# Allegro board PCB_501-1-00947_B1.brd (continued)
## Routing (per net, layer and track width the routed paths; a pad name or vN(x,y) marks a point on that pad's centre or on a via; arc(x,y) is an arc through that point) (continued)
MIPI_VREG_0P4V: length 1.2
  TOP w0.254: v2(55.77,85.77) 55.69,85.85 U7.H18
  BOTTOM w0.254: 55.37,86.26 55.77,85.86 v2(55.77,85.77)
MX7_ONOFF: length 75.1
  TOP w0.102: 69.48,88.95 v2(69.48,88.95) ; 69.48,88.95 U7.AC8 69.48,88.95
  TOP w0.127: C367.1 R249.1 ; R249.1 97.9,67.84 SW6.3 SW6.4 ; R249.1 92.74,67.84 92.3,68.28 92.3,70.08 89.43,72.95 89.43,81.59 91.94,84.09 96.01,84.09 98.39,86.47 v1(98.39,86.99)
  L6_INT_2 w0.102: 71.74,89.17 71.51,88.95 v2(69.48,88.95)
  L6_INT_2 w0.127: 71.74,89.17 75.13,89.17 77.66,86.65 78.01,86.65 78.86,85.8 81.77,85.8 82.62,86.65 87.33,86.65 88.18,87.51 97.88,87.51 v1(98.39,86.99)
MX7_RST_B: length 17.1
  TOP w0.254: v1(87.58,86.06) 84.66,88.97 84.66,92.44 86.33,94.11 D21.1 ; R347.1 C368.1 88.61,81.68 v1(87.9,82.39)
  L6_INT_2 w0.254: v1(87.9,82.39) 87.58,82.71 v1(87.58,86.06)
NVCC_DRAM_CKE: length 8.9
  TOP w0.137: v2(61,94.24) 60.99,94.24 60.99,93.72
  L6_INT_2 w0.127: v2(61,94.24) 60.46,94.24 59.77,94.93 59.77,94.93 59.56,95.15 59.55,95.15 59.24,95.46 59.24,95.46 59.03,95.68 58.31,95.68
  L6_INT_2 w0.305: v2(55.59,95.37) 55.9,95.68 58.31,95.68
  BOTTOM w0.254: R85.1 54.46,95.57 54.62,95.73 55.23,95.73 v2(55.59,95.37) 55.59,94.94 C140.1
OTG1_CHD_B: length 6.8
  TOP w0.102: U7.C7 58.35,77.81 v2(58.35,77.81)
  BOTTOM w0.102: 56.6,77.29 57.33,78.02 57.33,78.38 57.73,78.77 57.89,78.77 58.34,78.32 58.34,77.82 v2(58.35,77.81)
  BOTTOM w0.127: TP48.1 55.21,75.54 56.6,76.92 56.6,77.29
OTG1_REXT: length 5.8
  TOP w0.127: v1(55.77,73.18) 56.46,73.18 57.04,73.76 57.04,75.98 U7.A7
  BOTTOM w0.127: v1(55.77,73.18) 55.74,73.18 R66.2
OTG2_REXT: length 5.6
  TOP w0.127: R70.2 52.87,74.78 52.83,74.82 52.83,75.49 53.48,76.15 53.65,76.15 54.68,77.18 54.68,77.86 U7.A11
OTG_VBUS: length 1.5
  TOP w0.508: FB18.2 49.91,7.57 C298.1
  vias: v1(47.72,10.16) v1(47.72,9.02)
OTG_VBUS_CTRL: length 2.5
  BOTTOM w0.508: Q25.3 51,16.13 R570.1 50.88,15.99 Q24.1
OUT3: length 2.5
  TOP w0.254: v1(99.86,39.86) 99.79,39.79 U24.30
  BOTTOM w0.127: C276.1 100.34,39.86 v1(99.86,39.86)
OVRPRTC: length 2.4
  TOP w0.254: Q5.1 41.42,99.11 R8.2 40.99,99.59 R6.1
OVRPRTC_LED: length 2.9
  TOP w0.254: Q5.3 40.04,96.65 D2.1
OVRPRTC_LED_PWR: length 1.3
  TOP w0.254: R4.2 36.07,97.9 D2.2
PCIE_CLK_GEN_SCL: length 6.1
  TOP w0.137: v1(76.34,101.75) 76.34,101.67 U42.8
  BOTTOM w0.137: v1(76.34,101.75) 76.34,102.99 R595.1
PCIE_CLK_GEN_SDA: length 6.4
  TOP w0.137: U42.9 78.29,99.09 76.06,101.32 v1(75.81,101.32)
  BOTTOM w0.137: R596.1 75.81,103.6 v1(75.81,101.32)
PCIE_CLKGEN_SS_SEL: length 2
  TOP w0.127: R604.1 82.48,95.53 U42.23
PCIE_CTXM: length 2.7
  BOTTOM w0.137: C207.2 101.98,72.77 arc(101.9,72.89) 101.87,73.03 101.87,74.34 arc(101.93,74.67) J8.31
PCIE_CTXP: length 2.7
  BOTTOM w0.137: C208.2 101.47,72.77 arc(101.55,72.89) 101.58,73.03 101.58,74.34 arc(101.51,74.67) J8.33
PCIE_DIS_B: length 47.3
  TOP w0.102: U7.T2 68.42,81.55 68.98,80.99 68.98,80.45 69.32,80.11 69.89,80.11 v1(70.25,79.76)
  L6_INT_2 w0.102: v1(70.25,79.76) 70.86,79.76
  L6_INT_2 w0.127: v1(104.68,86.15) 92.56,86.15 85.72,79.31 82.43,79.31 81.48,78.36 72.99,78.36 71.59,79.76 70.86,79.76
  BOTTOM w0.127: J8.20 106.52,84.47 106.9,84.85 106.9,86.02 106.31,86.61 105.14,86.61 v1(104.68,86.15)
PCIE_REFCLK_N: length 10.6
  TOP w0.104: U7.AE10 68.95,91.19 69.42,91.67 arc(69.48,91.71) 69.55,91.72 70.05,91.72 70.16,91.6 70.46,91.6 70.58,91.72 70.88,91.72 71,91.6 71.3,91.6 71.41,91.72 71.42,91.72 arc(71.68,91.77) 71.91,91.92 71.91,91.93 arc(71.94,91.95) 71.96,91.97 arc(72.02,92.03) 72.07,92.08 72.07,92.08 arc(72.21,92.18) 72.38,92.21 R608.1 72.77,92.55 72.71,92.62 arc(72.68,92.65) 72.68,92.69 72.68,92.76 arc(72.69,92.82) 72.72,92.88 72.91,93.06 arc(72.94,93.08) 72.98,93.09 73.1,93.09 arc(73.14,93.08) 73.17,93.06 73.24,93 R607.2 73.56,93.32 arc(73.59,93.47) 73.68,93.6 arc(73.78,93.67) 73.91,93.69 74.38,93.69 arc(74.59,93.65) 74.77,93.53 74.98,93.32 arc(75.23,93.15) 75.53,93.1 77.22,93.1 R633.2
PCIE_REFCLK_P: length 10.5
  TOP w0.104: U7.AD10 68.61,90.73 68.61,91.21 68.61,91.25 69.23,91.87 arc(69.37,91.96) 69.55,92 71.29,92 arc(71.81,92.21) 72.03,92.73 72.03,92.92 72.22,92.92 arc(72.26,92.93) 72.29,92.95 72.8,93.46 arc(72.83,93.51) 72.84,93.58 R605.2 73.32,93.73 arc(73.41,93.75) 73.48,93.79 arc(73.68,93.93) 73.91,93.97 74.38,93.97 arc(74.7,93.91) 74.96,93.73 75.17,93.52 arc(75.34,93.41) 75.53,93.37 76.22,93.37 arc(76.28,93.39) 76.33,93.42 76.36,93.46 arc(76.39,93.49) 76.39,93.53 R632.2
PCIE_REFCLKOUT_N: length 71.8
  TOP w0.104: R598.2 75.12,94.96 arc(75.02,94.94) 74.93,94.9 74.93,94.91 arc(74.76,94.82) 74.58,94.79 74.44,94.79 arc(74.07,94.87) 73.77,95.07 73.7,95.14 arc(73.6,95.2) 73.5,95.22 v1(73.3,95.22) ; 67.89,90.01 68.42,90.01 v2(68.42,90.01)
  L3_INT_1 w0.117: v1(73.3,95.22) 73.3,95.39 arc(73.27,95.52) 73.19,95.64 arc(73.04,95.74) 72.85,95.78 72.68,95.78 arc(72.51,95.75) 72.38,95.66 72.05,95.32 arc(71.95,95.19) 71.88,95.04 arc(71.87,94.96) 71.87,94.89 71.87,93.29 arc(71.77,92.83) 71.51,92.44 arc(71.15,92.2) 70.73,92.11 arc(70.43,92.05) 70.18,91.88 68.42,90.13 v2(68.42,90.01)
  BOTTOM w0.104: R645.1 113.21,70.3 arc(113.12,70.18) 113.09,70.03 113.09,69.9 arc(113,69.46) 112.76,69.09 112.14,68.47 arc(110.69,67.51) 108.99,67.17 93.13,67.17 93.05,67.09 92.67,67.09 92.6,67.17 92.29,67.17 92.2,67.07 91.86,67.07 91.76,67.17 91.76,67.17 arc(89.96,67.52) 88.44,68.54 86.94,70.04 arc(85.43,72.3) 84.9,74.96 84.9,82.97 arc(84.73,83.83) 84.25,84.56 73.78,95.02 arc(73.56,95.17) v1(73.3,95.22)
PCIE_REFCLKOUT_N0: length 3.9
  BOTTOM w0.104: R645.2 113.13,71.89 arc(113.09,71.95) 113.07,72.02 arc(113.06,72.06) 113.06,72.09 arc(113.08,72.21) 113.15,72.32 R634.2 113.33,72.75 arc(113.13,73.05) 113.06,73.4 113.06,74.32 arc(113.13,74.66) J8.11
PCIE_REFCLKOUT_P: length 71.8
  TOP w0.104: U7.AB10 67.89,89.48 v2(67.89,89.48) ; R597.2 74.83,95.26 arc(74.82,95.21) 74.79,95.16 arc(74.7,95.09) 74.58,95.07 74.44,95.07 arc(74.18,95.12) 73.96,95.27 73.96,95.27 arc(73.83,95.47) v1(73.78,95.71)
  L3_INT_1 w0.117: v1(73.78,95.71) 73.7,95.71 arc(73.53,95.74) 73.39,95.83 arc(73.14,96) 72.85,96.06 72.68,96.06 arc(72.41,96) 72.18,95.85 71.85,95.52 arc(71.7,95.33) 71.61,95.1 71.59,95.08 71.59,93.29 arc(71.52,92.94) 71.31,92.63 arc(71.05,92.45) 70.73,92.39 arc(70.33,92.31) 69.98,92.08 68.08,90.18 arc(68.06,90.14) 68.05,90.1 68.05,89.68 arc(68.04,89.64) 68.01,89.6 v2(67.89,89.48)
  BOTTOM w0.104: R644.1 112.72,70.22 arc(112.79,70.12) 112.81,70.01 112.81,69.9 arc(112.75,69.57) 112.56,69.29 111.94,68.67 arc(110.59,67.76) 108.99,67.45 91.76,67.45 arc(90.07,67.78) 88.64,68.74 87.14,70.24 arc(85.69,72.41) 85.18,74.96 85.18,82.97 arc(84.99,83.94) 84.45,84.76 73.98,95.22 arc(73.98,95.22) 73.98,95.22 arc(73.83,95.45) v1(73.78,95.71)
PCIE_REFCLKOUT_P0: length 3.9
  BOTTOM w0.104: R644.2 112.69,71.85 arc(112.76,71.95) 112.78,72.06 112.78,72.17 arc(112.77,72.23) 112.74,72.28 R635.2 112.46,72.69 arc(112.7,73.05) 112.78,73.46 112.78,74.32 arc(112.71,74.66) J8.13
PCIE_REXT: length 3.3
  TOP w0.102: v2(65.22,91.07) 65.24,91.06 U7.AA13
  BOTTOM w0.102: v2(65.22,91.07) 65.79,91.07 66.77,92.05 67.59,92.05 R80.2
PCIE_RST_B: length 45.8
  TOP w0.102: 70.9,80.09 68.4,82.58 U7.T3
  TOP w0.127: v1(73.35,77.14) 73.17,77.14 71.85,78.46 71.85,78.82 71.09,79.59 71.09,79.9 70.9,80.09
  L6_INT_2 w0.127: v1(103.73,85.47) 103.52,85.68 92.67,85.68 86.02,79.03 82.54,79.03 81.59,78.08 73.86,78.08 73.35,77.57 v1(73.35,77.14)
  BOTTOM w0.127: J8.22 105.72,83.96 104.21,85.47 v1(103.73,85.47)
PCIE_RX_N: length 71.2
  TOP w0.102: U7.AE11 68.42,91.74 68.86,92.19 69.02,92.19 69.23,92.4 69.23,92.55 69.55,92.88
  TOP w0.137: 69.55,92.88 69.88,93.2 v1(70.46,93.2)
  BOTTOM w0.137: R96.1 arc(105.47,71.52) 105.43,71.5 105.14,71.2 arc(105.09,71.14) 105.08,71.06 105.08,70.85 arc(105.11,70.7) 105.19,70.58 105.24,70.53 arc(105.52,70.34) 105.86,70.27 106.47,70.27 arc(107.34,70.45) 108.07,70.94 108.08,70.95 arc(108.78,71.99) 109.02,73.23 109.02,73.51 108.87,73.65 108.87,74.05 109.02,74.2 109.02,74.67 108.82,74.87 108.82,75.22 109.02,75.42 109.02,75.69 arc(108.93,76.17) 108.65,76.57 arc(107.56,77.3) 106.28,77.56 106.01,77.56 105.85,77.39 105.46,77.39 105.3,77.56 104.91,77.56 104.75,77.39 104.37,77.39 104.2,77.56 103.82,77.56 103.65,77.39 103.27,77.39 103.1,77.56 102.72,77.56 102.55,77.39 102.17,77.39 102,77.56 97.41,77.56 97.25,77.4 96.89,77.4 96.73,77.56 96.37,77.56 96.21,77.4 95.85,77.4 95.69,77.56 95.34,77.56 95.17,77.4 94.82,77.4 94.65,77.56 94.3,77.56 94.14,77.4 93.78,77.4 93.62,77.56 93.35,77.56 arc(92.35,77.76) 91.49,78.33 91.11,78.71 arc(90.43,79.73) 90.19,80.93 90.19,81.6 arc(88.91,88.03) 85.27,93.49 83.04,95.71 82.81,95.71 82.54,95.99 82.54,96.22 82.27,96.49 82.04,96.49 81.76,96.76 81.76,96.99 81.49,97.27 81.26,97.27 80.99,97.54 80.99,97.77 79.55,99.21 arc(78.73,99.76) 77.76,99.95 76.68,99.95 76.52,99.79 76.16,99.79 76,99.95 75.74,99.95 arc(74.78,99.76) 73.96,99.21 73.78,99.03 73.78,98.8 73.52,98.55 73.3,98.55 73.04,98.29 73.04,98.07 72.79,97.81 72.56,97.81 71.54,96.79 arc(71.22,96.32) 71.11,95.76 71.11,94.78 arc(71,94.2) 70.67,93.71 arc(70.51,93.48) v1(70.46,93.2)
PCIE_RX_P: length 71.4
  TOP w0.102: 69.26,92.99 69.17,92.91 69.17,92.86 68.16,91.85 68.16,91.83 68.08,91.74 68.08,91.33 67.89,91.14 U7.AD11
  TOP w0.137: 69.26,92.99 69.98,93.72 v1(69.98,93.88)
  BOTTOM w0.137: v1(69.98,93.88) 70.17,93.88 arc(70.36,93.91) 70.54,94 arc(70.75,94.37) 70.82,94.78 70.82,95.76 arc(70.95,96.43) 71.33,96.99 73.76,99.42 arc(74.67,100.03) 75.74,100.24 77.76,100.24 arc(78.84,100.03) 79.75,99.41 85.48,93.69 arc(89.18,88.15) 90.48,81.6 90.48,80.93 arc(90.7,79.84) 91.32,78.92 91.7,78.54 arc(92.46,78.03) 93.35,77.85 106.28,77.85 arc(107.67,77.57) 108.86,76.78 arc(109.2,76.28) 109.31,75.69 109.31,73.23 arc(109.05,71.88) 108.29,70.74 arc(108.28,70.74) 108.28,70.73 arc(107.45,70.18) 106.47,69.98 105.86,69.98 arc(105.41,70.07) 105.04,70.32 104.98,70.38 arc(104.84,70.59) 104.79,70.85 104.79,71.06 arc(104.77,71.14) 104.73,71.2 104.43,71.5 arc(104.4,71.52) R97.1
PCIE_RXN_R: length 2.7
  BOTTOM w0.137: R96.2 105.23,72.77 arc(105.11,72.95) 105.07,73.15 105.07,74.34 arc(105.13,74.67) J8.23
PCIE_RXP_R: length 2.7
  BOTTOM w0.137: R97.2 104.71,72.84 arc(104.76,72.91) 104.78,73 104.78,74.34 arc(104.71,74.67) J8.25
PCIE_SMB_CLK: length 3.2
  BOTTOM w0.127: R506.1 102.65,86.24 102.65,85.29 102.58,85.22 102.58,83.21 J8.30
PCIE_SMB_DATA: length 3.3
  BOTTOM w0.127: R504.1 101.48,86.26 101.48,84.92 101.72,84.68 J8.32
PCIE_TX_N: length 56.4
  TOP w0.137: v2(67.89,90.54) 67.89,90.54 67.36,90.54
  BOTTOM w0.137: v2(67.89,90.54) arc(67.93,90.72) 68.03,90.88 69.24,92.09 arc(69.45,92.24) 69.69,92.33 arc(69.79,92.34) 69.89,92.36 arc(69.96,92.36) 70.02,92.36 70.97,92.36 arc(71.43,92.45) 71.82,92.71 72.01,92.9 arc(72.25,93.26) 72.34,93.7 72.34,94.85 arc(72.48,95.55) 72.88,96.15 73.17,96.45 arc(73.5,96.67) 73.9,96.75 73.92,96.75 arc(74.31,96.67) 74.64,96.45 74.83,96.26 74.83,96.05 75.11,95.76 75.32,95.76 75.61,95.48 75.61,95.27 75.89,94.99 76.1,94.99 76.38,94.7 76.38,94.49 76.67,94.21 76.88,94.21 84.46,86.63 arc(86.19,84.04) 86.8,80.98 86.8,77.59 arc(87.38,74.67) 89.03,72.2 89.12,72.11 arc(92.33,69.96) 96.12,69.21 96.4,69.21 96.55,69.06 96.95,69.06 97.1,69.21 97.5,69.21 97.65,69.06 98.05,69.06 98.19,69.21 99.21,69.21 arc(100.35,69.43) 101.31,70.07 101.58,70.35 arc(101.79,70.66) 101.87,71.03 arc(101.89,71.13) 101.94,71.22 102.2,71.48 arc(102.23,71.5) C207.1
PCIE_TX_P: length 56.4
  TOP w0.137: v2(67.36,90.01) 67.36,90.01 66.83,90.01 U7.AB11
  BOTTOM w0.137: C208.1 arc(101.21,71.5) 101.24,71.48 101.49,71.22 arc(101.55,71.13) 101.57,71.03 arc(101.52,70.77) 101.38,70.56 101.1,70.28 arc(100.23,69.7) 99.21,69.5 96.12,69.5 arc(92.44,70.23) 89.32,72.32 89.24,72.4 arc(87.65,74.78) 87.09,77.59 87.09,80.98 arc(86.46,84.15) 84.66,86.84 74.84,96.66 arc(74.42,96.94) 73.92,97.04 73.9,97.04 arc(73.39,96.94) 72.97,96.65 72.67,96.36 arc(72.21,95.67) 72.05,94.85 72.05,93.7 arc(71.98,93.38) 71.8,93.11 71.62,92.92 arc(71.32,92.72) 70.97,92.65 70.02,92.65 arc(69.88,92.65) 69.73,92.63 arc(69.68,92.62) 69.64,92.61 arc(69.31,92.5) 69.03,92.29 67.6,90.86 arc(67.54,90.76) 67.51,90.65 67.51,90.38 arc(67.47,90.18) v2(67.36,90.01)
PCIE_UIM_CLK: length 15.9
  TOP w0.127: J7.C3 104.87,91.86 104.87,91.19 109.52,86.54 v1(112.92,86.54)
  BOTTOM w0.127: J8.12 v1(112.92,86.54)
PCIE_UIM_DATA: length 19.8
  TOP w0.137: J7.C7 127.6,92.46 127.6,92.09 120.67,85.16 114.75,85.16 114.31,84.72 v1(113.79,84.72)
  BOTTOM w0.137: v1(113.79,84.72) 113.72,84.65 J8.10
PCIE_UIM_PWR: length 16.5
  TOP w0.508: C571.1 103.26,88.39 J7.C1 106.34,88.07 108.98,85.43 114.35,85.43 v1(114.52,85.6)
  BOTTOM w0.508: J8.8 v1(114.52,85.6)
PCIE_UIM_RST: length 12.4
  TOP w0.127: v1(105.08,89.71) 104.56,89.71 103.66,90.61 J7.C2
  BOTTOM w0.127: J8.14 112.12,84.43 110.83,85.72 109.07,85.72 v1(105.08,89.71)
PCIE_UIM_VPP: length 21.3
  TOP w0.137: J7.C6 121.81,84.13 111.77,84.13 111.32,84.58 v1(111.32,84.6)
  BOTTOM w0.137: J8.16 v1(111.32,84.6)
PCIE_USB_DM: length 3.3
  BOTTOM w0.127: FL3.4 100.06,86.05 99.8,85.79 99.8,84.6 100.12,84.28 J8.36
PCIE_USB_DP: length 3.3
  BOTTOM w0.127: FL3.1 99.26,86.02 99.53,85.75 99.53,84.49 99.32,84.29 J8.38
PHY_CLKOUT: length 10.9
  TOP w0.127: TP62.1 v1(47.72,34.29) ; v1(41.11,33.4) 40.22,34.29 U13.18
  BOTTOM w0.127: v1(47.72,34.29) 46.67,34.29 45.78,33.4 v1(41.11,33.4)
PHY_CT: length 3.1
  TOP w0.508: J27.1 22.55,19.86 C576.1
PHY_GPIO0: length 7.4
  TOP w0.127: R664.1 R666.2 26.61,37.21 30.9,37.21 31.82,36.29 U13.39
PHY_GPIO1: length 7.4
  TOP w0.127: U13.40 31.85,35.79 31.8,35.84 31.77,35.84 30.81,36.8 27.02,36.8 R667.2 R665.1
PHY_INT_B: length 2.2
  TOP w0.127: R680.1 30.83,33.53 31.1,33.79 U13.44
PHY_JTAG: length 4.8
  TOP w0.127: 39.17,36.29 39.2,36.29 39.49,36.01 39.49,35.58 39.2,35.29 U13.20 ; 39.17,36.29 U13.22 ; 39.17,36.29 39.28,36.41 39.28,36.59 39.08,36.79 38.95,36.79 ; v1(39.81,36.91) 39.77,36.86 39.02,36.86 38.95,36.79 ; 38.95,36.79 U13.23
  BOTTOM w0.127: R741.1 40.07,37.16 v1(39.81,36.91)
PHY_LED0: length 12.6
  TOP w0.127: v1(24.6,33.78) 23.73,34.66 D14.2 ; U13.47 32.07,32.26 31.38,32.26 31.06,31.95 28.74,31.95 28.03,31.24 R668.2 R663.1 26.89,31.62 27.3,32.03 v1(27.32,32.03)
  BOTTOM w0.127: v1(24.6,33.78) 26.35,32.03 v1(27.32,32.03)
PHY_LED1: length 46.7
  TOP w0.127: J27.13 30.6,8.64 20.03,8.64 19.02,9.65 19.02,23.24 24.1,28.32 24.1,30.73 24.58,31.22 R301.1 R307.2 25.75,31.24 27.03,32.53 27.63,32.53 27.72,32.44 30.88,32.44 31.24,32.79 U13.46
PHY_LED2: length 40.6
  TOP w0.127: J27.12 24.25,6.83 22.95,8.13 20.03,8.13 18.7,9.46 18.7,27.6 R302.1 R308.2 25.14,32.89 30.7,32.89 31.1,33.29 U13.45
PHY_MDI_A_M: length 19.7
  TOP w0.104: J27.3 25.27,19.46 24.92,18.75 24.37,18.75 24.1,19.02 24.1,20.83 25.12,21.85 25.12,22.56 25.14,22.95 U53.2 U53.9 25.14,24.06 25.14,24.66 28.39,27.91 31.18,27.91 33.17,29.9 33.17,30.54 33.28,30.65 U13.2
PHY_MDI_A_P: length 19.7
  TOP w0.104: U13.1 32.78,30.65 32.89,30.54 32.89,30.01 31.06,28.19 28.28,28.19 24.86,24.77 24.86,24.06 U53.10 U53.1 24.84,22.97 24.84,21.97 23.82,20.94 23.82,18.9 24.25,18.47 24.35,18.16 J27.2
PHY_MDI_B_M: length 19.4
  TOP w0.104: J27.5 27.76,19.61 27.28,18.66 27,18.66 26.64,19.02 26.64,22.93 U53.5 26.67,23.12 26.67,23.87 U53.6 26.64,24.06 26.64,24.66 27.47,25.49 30.41,25.49 34.67,29.75 34.67,30.54 34.78,30.65 U13.5
PHY_MDI_B_P: length 19.4
  TOP w0.104: J27.4 26.89,18.15 26.78,18.48 26.36,18.9 26.36,22.93 U53.4 26.33,23.12 26.33,23.87 U53.7 26.36,24.06 26.36,24.77 27.35,25.77 30.29,25.77 34.39,29.86 34.39,30.54 34.28,30.65 U13.4
PHY_MDI_C_M: length 19.4
  TOP w0.104: U13.8 36.28,30.65 36.17,30.54 36.17,29.05 32.9,25.78 31.9,25.78 30.98,24.86 30.98,24.06 U54.9 31.01,23.87 31.01,23.12 U54.2 30.98,22.95 30.98,22.13 30.53,21.68 30.05,21.68 29.67,22.05 29.42,22.05 29.24,21.87 29.24,21.62 29.61,21.25 29.61,20.76 29.18,20.33 29.18,18.88 29.49,18.58 29.82,18.69 30.29,19.63 J27.7
PHY_MDI_C_P: length 19.3
  TOP w0.104: J27.6 29.4,18.09 29.36,18.3 28.9,18.77 28.9,20.44 29.33,20.88 29.33,21.13 28.96,21.5 28.96,21.99 29.3,22.33 29.79,22.33 30.16,21.96 30.41,21.96 30.7,22.25 30.7,22.95 U54.1 30.67,23.15 30.67,23.87 U54.10 30.7,24.06 30.7,24.97 31.79,26.06 32.79,26.06 35.89,29.16 35.89,30.54 35.78,30.65 U13.7
PHY_MDI_D_M: length 19.5
  TOP w0.104: J27.9 32.84,19.61 32.35,18.63 32.17,18.57 31.72,19.02 31.72,20.95 32.48,21.72 32.48,22.93 U54.5 32.49,23.15 32.49,23.84 U54.6 32.59,24 32.48,24.11 32.48,24.51 32.73,24.77 33.88,24.77 34.56,25.45 34.82,25.45 35.33,24.94 35.82,24.94 36.16,25.28 36.16,25.76 35.64,26.28 35.64,26.53 37.67,28.56 37.67,30.54 37.78,30.65 U13.11
PHY_MDI_D_P: length 19.4
  TOP w0.104: U13.10 37.28,30.65 37.39,30.54 37.39,28.67 35.36,26.65 35.36,26.16 35.88,25.65 35.88,25.39 35.7,25.22 35.45,25.22 34.93,25.73 34.45,25.73 33.76,25.04 32.62,25.04 32.2,24.63 32.2,24.05 U54.7 32.17,23.87 32.17,23.12 U54.4 32.2,22.93 32.2,21.83 31.44,21.07 31.44,18.9 31.96,18.38 32.01,18.23 J27.8
PHY_RBIAS: length 2
  TOP w0.254: U13.12 v1(38.28,30.23)
  BOTTOM w0.508: v1(38.28,30.23) 38.94,29.57 R669.1
PHY_XI: length 5
  TOP w0.137: U13.15 41.75,32.79 C305.1 43.76,33.05 X3.1
PHY_XO: length 5.2
  TOP w0.137: R130.2 41.98,32 C304.1 44.55,31.98 45.52,31 X3.3
PMIC_AC_DET: length 22.2
  TOP w0.127: SW9.2 39.34,87.88 37.36,89.87 C556.2 27.92,89.98 Q37.3 23.88,90.07 R448.1 21.68,89.94 21.68,89.66 19.9,87.87 U5.9
PMIC_ENABLE: length 111.1
  TOP w0.102: v2(68.95,88.42) 68.95,88.42 U7.AB8
  TOP w0.127: R350.1 90.24,94.91 90.31,94.83 v1(90.31,92.79)
  TOP w0.152: U5.46 17.88,83.43 18,83.31 18,83.31 18.42,82.88 18.42,82.48 19.08,81.83 19.33,81.58 19.33,81.58 R735.2 v1(20.13,81.38)
  L6_INT_2 w0.102: 71.96,90.29 70.98,89.3 69.33,89.3 68.95,88.92 v2(68.95,88.42) 68.4,88.42 60.11,96.71
  L6_INT_2 w0.127: v1(90.31,92.79) 85.02,87.51 82.01,87.51 80.89,86.38 79.9,86.38 75.99,90.29 71.96,90.29 ; 60.11,96.71 58.14,98.68 47.59,98.68 44.93,101.34 32.85,101.34 32.07,100.56 24.14,100.56 19.85,96.27 19.85,94.35 20.7,93.51 20.7,91.5 21,91.19 21,88.72 22.27,87.45 23.03,87.45 23.16,87.32 23.16,85.57 20.82,83.22 19.14,83.22 19.02,83.1 19.02,81.81 19.45,81.38 v1(20.13,81.38)
  BOTTOM w0.152: v1(20.13,81.38) R735.2
PMIC_ENABLE_ACDET: length 74.4
  TOP w0.127: v1(87.6,97.28) 89.48,97.28 R736.1 ; Q37.1 33.84,92.14 37.08,95.38 43.15,95.38 44.53,96.76 46.51,96.76 49.39,99.64 49.39,101.09 v1(48.45,102.04)
  L6_INT_2 w0.127: v1(87.6,97.28) 84.44,97.28 81.87,99.85 74.22,99.85 73.43,100.63 49.85,100.63 v1(48.45,102.04)
PMIC_GPIO1: length 380.5
  TOP w0.127: v1(5.55,94.78) 5.55,93.54 6.79,92.3 R749.1 11.52,92.7 v1(11.09,93.14) ; v1(104.93,58.99) 112.35,66.41 U46.5 ; U47.3 28.59,47.19 v1(28.67,47.12) ; R762.2 20.92,96.44 20.79,96.32 v2(20.79,95.99)
  TOP w0.203: v1(81.38,110.03) U51.7 ; U49.3 v1(63.52,37.08)
  L6_INT_2 w0.127: v1(19.5,56.22) 19.92,56.22 20.39,56.69 20.39,59.26 18.95,60.69 18.95,62.36 28.6,72.01 28.6,76.79 26.92,78.47 21.72,78.47 20.81,77.56 10.81,77.56 8.18,80.18 8.18,81.01 8.41,81.24 8.41,88.02 7.79,88.64 7.79,90.57 10.36,93.14 v1(11.09,93.14) ; v1(28.67,47.12) 28.67,42.67 28.86,42.48 28.86,35.62 28.22,34.98 28.22,30.3 28.67,29.85 28.67,28.85 32.31,25.21 62.43,25.21 63.52,26.3 v1(63.52,37.08) 64.45,38.01 82.82,38.01 84.13,36.7 84.13,33.37 85.58,31.93 110.22,31.93 110.63,32.34 110.63,33.74 110.55,33.83 110.55,34.19 110.63,34.28 110.63,41.34 111.47,42.18 111.47,52.44 v1(104.93,58.99) ; v1(81.38,110.03) 82.98,111.63 82.98,117.52 79.3,121.2 72.3,121.2 71.1,122.39 44.28,122.39 35.53,113.64 35.53,103.76 35.08,103.3 13.89,103.3 5.55,94.97 v1(5.55,94.78)
  BOTTOM w0.127: v1(11.09,93.14) 11.94,93.99 13.5,93.99 15.11,95.61 20.41,95.61 v2(20.79,95.99) ; v1(104.93,58.99) 103.36,58.99 101.87,60.48 101.87,61.77 U55.A3 ; v1(19.5,56.22) 23.1,56.22 23.29,56.04 23.29,52.71 28.67,47.32 v1(28.67,47.12)
PMIC_I2C1_SCL: length 4.5
  TOP w0.137: U5.3 19.49,85.43 19.99,85.43 20.88,84.55 21.73,84.55 21.87,84.41 v1(22.63,84.41)
  BOTTOM w0.137: v1(22.63,84.41) 22.63,85 R232.2
PMIC_I2C1_SDA: length 5.8
  TOP w0.137: v1(23.19,83.99) 23.19,83.98 21.92,83.98 21.62,84.28 20.77,84.28 19.99,85.07 U5.2
  BOTTOM w0.137: v1(23.19,83.99) 23.19,84.43 R236.2
PMIC_INT_B: length 113.2
  TOP w0.127: U7.N5 65.24,81.54 65.25,81.53 v2(65.25,81.51)
  TOP w0.152: R47.2 v1(18.76,80.42)
  L3_INT_1 w0.102: v2(65.25,81.51) 65.21,81.51 65.11,81.42 63.51,81.42 62.22,80.12 60.78,80.12 60.05,80.85 57.65,80.85 54.32,77.52 54.32,77.3
  L3_INT_1 w0.127: 54.32,77.3 54.32,77.26 52.46,75.4 52.46,71.98 51.49,71.01 51.49,65.31 50.72,64.53 v1(50.72,49.87)
  L6_INT_2 w0.127: v1(23.78,55.4) 23.78,56 23.2,56.58 23.2,63.3 29.16,69.27 29.16,77.25 26.47,79.95 20.13,79.95 19.66,80.42 v1(18.76,80.42) ; v1(50.72,49.87) 49.99,49.15 33.88,49.15 v1(32.33,47.6)
  BOTTOM w0.127: v1(23.78,55.4) 23.78,52.6 28.79,47.6 v1(32.33,47.6) ; R47.2 v1(18.76,80.42)
PMIC_PB_B: length 43.5
  TOP w0.127: U5.44 17.08,83.49 17.79,82.78 17.79,82.77 17.87,82.69 17.87,82.04 17.51,81.67 17.51,81.57 v1(17.49,81.56)
  TOP w0.254: v1(7.21,65.79) 7.87,65.79 8.12,66.04 R689.1 7.71,66.55 6.54,67.72 SW4.4 SW4.3
  L3_INT_1 w0.254: v1(7.21,65.79) 7.21,74.81 7.18,74.84 7.18,77.52 8.98,79.32 v1(8.98,80.41)
  L6_INT_2 w0.254: v1(17.49,81.56) 17.49,79.98 15.85,78.34 11.05,78.34 v1(8.98,80.41)
PMIC_PFI: length 3.7
  TOP w0.127: U5.16 17.51,89.88 17.51,90.22 16.91,90.82 16.79,90.82 v1(16.55,91.06)
  BOTTOM w0.127: v1(16.55,91.06) 16.55,91.5 R40.2 18.01,91.8 R31.1
PMIC_PFO_B: length 65.8
  TOP w0.102: U7.N3 v2(66.3,80.46)
  TOP w0.127: U5.10 19.94,88.27 21.22,89.56 21.22,93.77 21.81,94.36 R686.2 v1(22.34,95)
  L6_INT_2 w0.102: v2(66.3,80.46) 66.27,80.43 65.77,80.43 64.91,79.57 64.56,79.57 64.38,79.76 64.03,79.76 63.82,79.55 62.41,79.55 62.08,79.88 61.05,79.88 57.97,82.97 57.97,83.26 58.17,83.47 58.17,85.54 56.99,86.73 55.7,86.73 55.39,87.04 55.39,88.49 54.46,89.42 54.46,89.63 54.25,89.83 53.96,89.83 53.7,89.57 48.66,89.57
  L6_INT_2 w0.127: 48.66,89.57 35.11,89.57 34.43,90.25 34.43,94.13 32.85,95.71 23,95.71 22.34,95.05 v1(22.34,95)
PMIC_PWR: length 25.6
  TOP w0.203: v1(12.14,86.54) 12.14,86.54 12.41,86.27 U5.32 ; v3(21.12,86.79) 21.01,86.67 U5.6
  TOP w0.254: R448.2 21.81,91.66 v1(21.68,91.79) ; R738.2 v1(7.05,87.78)
  TOP w0.381: R689.2 9.09,67.21 7.71,68.58 v1(7.71,75.06)
  L3_INT_1 w0.508: v1(7.71,75.06) 8.18,75.52 8.97,75.52 10.51,77.06 10.51,81.41 11.83,82.74 v3(11.83,82.8)
  BOTTOM w0.254: v1(21.68,91.79) 21.53,91.94 20.17,91.94
  vias: v1(11.53,86.51) v1(20.08,84.27) v1(20.55,83.92) v3(5.94,108.46) v3(5.94,106.05) v3(6.97,109.87) v3(8.73,112.9) v3(8.73,110.74) v3(10.11,114.25) v3(11.52,112.78) v3(11.65,110.87) v3(12.29,115.68) v3(12.68,83.8) v3(12.91,114.12) v3(13.62,84.13) v3(14.5,116.66) v3(14.54,114.95) v3(14.56,113.03) v3(14.57,110.87) v3(16.51,114.06) v3(16.69,115.9) v3(16.64,111.77) v3(16.68,109.24) v3(17.29,82.57) v3(18.63,116.96) v3(18.61,114.95) v3(18.62,113.03) v3(18.64,110.87) v3(18.76,107.95) v3(19.83,89.56) v3(20.35,90.08) v3(118.84,64.14) v3(118.84,62.87) v3(118.84,61.59) v3(119.6,64.77) v3(119.6,63.5) v3(119.6,62.23) v3(119.6,60.96)
PMIC_SD_VSEL: length 71.6
  TOP w0.102: U7.R1 68.45,80.99 68.67,80.77 68.67,80.27 69.32,79.63 v1(69.69,79.63)
  L6_INT_2 w0.102: v1(69.69,79.63) 70.41,78.91 70.41,78.58 70.47,78.52
  L6_INT_2 w0.127: 70.47,78.52 72.3,76.7 74.5,76.7 75.02,77.22 81.38,77.22 82.78,78.62 86.59,78.62 92.03,84.06 107.29,84.06 108.3,83.06 108.3,67.95 v1(106.71,66.37)
  BOTTOM w0.127: U55.B3 103.7,62.89 R742.2 106.19,61.72 106.67,62.19 106.67,65.06 106.68,65.07 106.68,66.32 106.71,66.35 v1(106.71,66.37)
PMIC_STBY: length 115.5
  L3_INT_1 w0.127: v2(19.58,93.25) 16.27,89.94 14.47,89.94 14.11,90.31 12.5,90.31 12.16,89.96 9.5,89.96 8.89,89.35 8.89,87.32 9.1,87.1 9.1,81.65 v2(9.4,81.35)
  L6_INT_2 w0.102: 58.28,99.2 60.16,99.2 67.67,91.69 70.56,91.69
  L6_INT_2 w0.127: v2(80.61,87.08) 79.74,87.08 76.22,90.6 72.35,90.6 71.26,91.69 70.56,91.69 ; 58.28,99.2 47.81,99.2 45.36,101.65 32.64,101.65 31.97,100.98 22.33,100.98 19.23,97.88 19.23,93.59 v2(19.58,93.25)
  BOTTOM w0.102: 73.28,88.41 72.58,89.12 71.9,89.12 71.44,88.66 71.44,88.28 69.82,86.66 69.64,86.66 69.4,86.91 R753.1
  BOTTOM w0.127: v2(80.61,87.08) 80.16,87.52 79.3,87.52 79.12,87.7 78.37,87.7 77.61,88.46 75.11,88.46 74.5,87.85 73.84,87.85 73.28,88.41 ; v2(9.4,81.35) 12.15,81.35 12.82,80.68 12.82,78.68 12.52,78.39 Q41.1
PMIC_STBY_R: length 1.4
  TOP w0.102: v2(70.01,88.42) 70.01,88.42 U7.AC7
  BOTTOM w0.102: R753.2 70.01,87.61 v2(70.01,88.42)
PMIC_WAKE_B: length 58.4
  TOP w0.127: U5.40 15.48,83.48 15.36,83.37 15.36,81.99 14.93,81.56 v1(14.93,80.49) ; v1(47.72,93.66) 47.72,92.68 48.49,91.91 51.21,91.91 52.51,90.6 U7.J25
  L3_INT_1 w0.127: v1(47.72,93.66) 43.59,93.66 42.89,92.96 41.82,92.96 26.29,77.43 26.28,77.43 22.89,74.04 19.77,74.04 19.3,73.57 v1(17.7,73.57)
  BOTTOM w0.127: v1(17.7,73.57) 15.87,75.4 R751.2 15.08,80.49 v1(14.93,80.49)
POR_B: length 154.8
  TOP w0.102: v2(65.77,84.16) 65.77,84.16 U7.R6
  TOP w0.127: v1(83.55,77.8) 80.56,74.81 v1(80.22,74.81) ; v1(32.76,93.37) R750.1 23.33,93.37 R690.2 23.31,93.68 23.15,93.84 21.93,93.84 v1(21.67,93.58) ; v1(6.06,91.36) 6.06,90.81 5.76,90.5 Q40.1
  L3_INT_1 w0.102: 67.82,86.83 67.82,89.02 67.52,89.32 67.52,89.63 67.73,89.85 67.73,90.16 67.52,90.38 67.5,90.38 66.42,91.46 66.13,91.46 65.92,91.24 65.62,91.24 65.4,91.46 65.07,91.46 64.85,91.24 64.52,91.24 64.04,91.72 64.03,91.72 63.85,91.9 63.68,91.9 62.55,93.02
  L3_INT_1 w0.127: v1(6.06,91.36) 10.59,91.36 11.09,91.86 13.77,91.86 16.59,91.86 18.86,94.13 21.12,94.13 v1(21.67,93.58) ; v1(119.98,94.49) 119.98,86.84 114.93,81.79 v1(107.43,81.79)
  L3_INT_1 w0.137: 62.55,93.02 59.56,93.02 58.5,91.96 58.18,91.96 57.97,91.75 57.96,91.75 57.48,91.27 57.48,91.27 57.44,91.23 57.13,91.23 56.93,91.43 56.92,91.43 56.91,91.44 56.6,91.44 56.4,91.24 56.39,91.24 56.38,91.23 56.07,91.23 54.91,92.38 53.34,92.38 53.34,92.39 50.99,92.39 49.19,94.19 39.88,94.19 39,93.32 32.81,93.32 v1(32.76,93.37) ; v2(65.77,84.16) 65.33,84.6 65.33,85.07 66.4,86.14 67.12,86.14 67.82,86.83
  L6_INT_2 w0.127: v1(83.55,77.8) 86.35,77.8 91.91,83.36 105.86,83.36 v1(107.43,81.79)
  BOTTOM w0.102: v2(65.77,84.16) 66.32,84.16 67.24,85.09 67.53,85.09 68.8,83.82 69.15,83.82 69.45,84.11 69.6,84.12 69.65,84.12 69.69,84.16 69.78,84.24 70.92,84.24 72.36,82.8 72.74,82.8 72.94,82.6
  BOTTOM w0.127: v1(80.22,74.81) 80.22,75.32 72.94,82.6 ; v1(119.98,94.49) 119.98,96.68 D26.2
PSU_5V0: length 15.7
  TOP w0.381: R613.2 v1(15.21,120.4)
  BOTTOM w0.381: v1(15.21,105.92) 15.59,106.3 15.59,120.02 v1(15.21,120.4)
PWR_LED: length 1.6
  TOP w0.508: R1.2 30.2,96.9 D1.2
PWR_OV_BASE: length 6
  TOP w0.381: Q17.1 42.7,110.8 45.46,113.56 R537.1
PWR_OV_CTL: length 3.9
  TOP w0.381: R538.1 45.28,116.97 46.07,116.18 D17.1 R537.2
QSPIA_DA0: length 36.3
  TOP w0.127: v2(57.81,91.07) 57.81,91.07 U7.P20
  L6_INT_2 w0.102: 53.12,92.04 54.92,92.04 56.29,90.66 56.86,90.66 57.27,91.07 v2(57.81,91.07)
  L6_INT_2 w0.127: v1(42.38,93.52) 41.32,92.46 39.6,92.46 39.31,92.75 39.31,93.39 40.28,94.36 43.58,94.36 45.01,92.93 48.76,92.93 49.09,92.6 52.06,92.6 52.63,92.04 53.12,92.04
  BOTTOM w0.137: U11.5 42.33,103.32 41.18,102.18 41.18,94.73 v1(42.38,93.52)
QSPIA_DA1: length 36.6
  TOP w0.102: v2(57.28,91.6) U7.P21
  L6_INT_2 w0.102: 55.7,92.64 56.73,91.6 v2(57.28,91.6)
  L6_INT_2 w0.127: v1(44.87,94.87) 44.61,95.12 38.7,95.12 38.57,95.25 38.57,95.76 38.7,95.89 42.7,95.89 43.59,96.77 47.78,96.77 49.98,94.57 49.98,93.93 50.11,93.8 50.48,93.8 50.61,93.94 50.61,94.21 50.74,94.34 51.17,94.34 51.4,94.56 51.4,95.25 51.57,95.42 51.82,95.42 52.46,94.78 52.46,94.57 51.87,93.98 51.87,93.8 52.45,93.23 53.66,93.23 53.79,93.35 53.79,93.83 53.92,93.95 54.22,93.95 54.35,93.83 54.35,92.94 54.5,92.79 54.75,92.79 54.91,92.94 54.91,93.65 55.06,93.8 55.39,93.8 55.67,93.52 55.67,93.32 55.49,93.14 55.49,92.84 55.7,92.64
  BOTTOM w0.137: U11.2 v1(44.87,94.87)
QSPIA_DA2: length 36.7
  TOP w0.102: U7.N20 v2(57.28,90.54)
  L6_INT_2 w0.102: v2(57.28,90.54) 57.28,89.95 57.55,89.68 57.55,89.44 57.43,89.32 57.08,89.32 56.64,89.76 56.64,89.95 54.82,91.77 52.44,91.77
  L6_INT_2 w0.127: v1(44.67,91.78) 43.78,91.78 43.28,91.28 37.7,91.28 37.57,91.41 37.57,91.76 37.79,91.98 41.9,91.98 43.26,93.34 44.04,93.34 44.87,92.51 47.46,92.51 48.09,91.87 48.66,91.87 49.09,92.31 51.9,92.31 52.44,91.77
  BOTTOM w0.137: U11.3 43.6,92.9 44.67,91.82 v1(44.67,91.78)
QSPIA_DA3: length 36.6
  TOP w0.102: v2(56.75,91.07) U7.N21
  L6_INT_2 w0.102: v2(56.75,91.07) 56.24,91.07 55.06,92.25
  L6_INT_2 w0.127: v1(38.65,94.06) 39.17,94.06 39.84,94.74 43.73,94.74 45.23,93.24 47.51,93.24 47.53,93.22 49.21,93.22 49.54,92.88 52.35,92.88 52.88,92.35 54.96,92.35 55.06,92.25
  BOTTOM w0.137: v1(38.65,94.06) 40.76,96.18 40.76,102.82 43.07,105.13 44.58,105.13 44.87,104.84 U11.7
QSPIA_SCLK: length 36.5
  TOP w0.102: v2(56.75,88.99) 56.76,88.99 56.76,89.47 U7.M20
  L6_INT_2 w0.127: v1(44.35,104.62) 38.97,104.62 38.58,104.23 38.58,103.2 39.06,102.72 46.38,102.72 v1(47.1,101.99)
  BOTTOM w0.137: v2(56.75,88.99) 56.19,88.99 51.06,94.12 49.28,94.12 48.15,95.24 48.15,100.94 v1(47.1,101.99) ; v1(44.35,104.62) 44.01,104.62 43.6,104.21 U11.6
QSPIA_SS0_B: length 36.7
  TOP w0.102: v2(55.69,90.01) U7.M21
  L6_INT_2 w0.102: 49.3,90.21 49.9,90.21 50.05,90.36 50.05,90.87 50.2,91.02 50.41,91.02 50.56,90.87 50.56,90.36 50.71,90.21 50.92,90.21 51.07,90.36 51.07,90.87 51.22,91.02 51.43,91.02 51.57,90.87 51.57,90.36 51.72,90.21 51.93,90.21 52.08,90.36 52.08,90.87 52.23,91.02 52.44,91.02 52.59,90.87 52.59,90.36 52.74,90.21 53.12,90.21 53.95,91.04 54.62,91.04 55.14,90.52 55.14,89.19 55.86,88.48 55.86,87.24 56.02,87.07 56.56,87.07 56.89,87.4 56.89,88.22 55.69,89.41 v2(55.69,90.01)
  L6_INT_2 w0.127: v1(49.58,91.4) 49.22,91.04 44.39,91.04 44.18,90.83 44.18,90.34 44.31,90.21 49.3,90.21
  BOTTOM w0.137: U11.1 46.19,95.65 R92.2 46.64,93.07 48.31,91.4 v1(49.58,91.4)
RES_BUCK_FB: length 0.7
  TOP w0.254: R694.1 R695.2
RES_CAN_STB: length 14.6
  TOP w0.102: U7.L20 56.22,89.49 v2(56.22,89.49)
  TOP w0.127: R381.2 44.67,92.46 45.39,91.74 v1(45.39,91.57)
  L6_INT_2 w0.102: 51.67,91.95 52.12,91.5 54.7,91.5 56.22,89.98 v2(56.22,89.49)
  L6_INT_2 w0.127: 51.67,91.95 49.42,91.95 49.04,91.57 v1(45.39,91.57)
RES_INT_B: length 3
  TOP w0.127: U5.45 17.48,83.45 18.13,82.8 18.13,82.39 18.35,82.18 18.35,81.6 R47.1
RES_LCD1_PWM: length 1.6
  TOP w0.254: R758.2 8.88,53.47 D35.2
RES_LED_BOOT_COMP: length 2.4
  TOP w0.127: DA1.1 46.62,93.3 45.9,94.02 R739.1
RES_LED_BOOT_PROC: length 2
  TOP w0.127: DA1.2 45.98,92.67 44.76,93.89 R740.1
RES_PHY_LED0: length 1.5
  TOP w0.381: D14.1 22.43,33.17 R293.1
RES_PHY_LED1: length 3.4
  BOTTOM w0.508: J27.14 35.04,6.88 R303.1
RES_PHY_LED2: length 3.7
  TOP w0.508: R297.1 21.64,6.88 J27.11
RES_PMIC_LED: length 2.2
  TOP w0.127: D33.2 R738.1
RES_POR_B: length 8.4
  TOP w0.127: R690.1 22.34,93 22.22,92.87 v1(21.67,92.87) ; v1(21.82,89.01) 21.8,89.01 21.38,88.59 20.98,88.59 19.96,87.58 19.85,87.47 U5.8
  L6_INT_2 w0.127: v1(21.67,92.87) 22.32,92.22 22.32,89.51 v1(21.82,89.01)
RES_SD1_RST: length 2.2
  BOTTOM w0.127: R108.2 107.25,50.07 106.25,51.07 Q8.1
RES_TP_BUSY: length 5.6
  TOP w0.127: R380.1 50.39,92.71 51.38,92.71 53.01,91.07 U7.K25
RES_VDD_SD_CON: length 3.3
  BOTTOM w0.254: Q7.3 95.79,60.58 97.88,60.58 R103.2
RGMII1_RX_CTL: length 69.2
  TOP w0.102: U7.E15 v2(55.16,83.11)
  TOP w0.137: v1(37.79,56.08) 36.83,56.08 35.78,55.03 35.78,49.25 29.3,42.77 R283.2
  L6_INT_2 w0.127: v1(37.79,56.08) 37.21,56.66 37.21,56.92 37.57,57.28 37.84,57.28 39.04,56.08 40.56,56.08 42.3,57.82 42.3,62.65 47.87,68.22 47.87,77.11 49.6,78.84 49.6,80.39 48.65,81.34 48.65,82.64 49.23,83.22 50.92,83.22 51.56,82.59 51.56,81.08 52,80.64 52,79.69 52.44,79.26 53.3,79.26 53.5,79.06 54.23,79.06 54.46,79.29 54.46,79.52 54.92,79.98 54.92,80.78 55.68,81.54 55.68,82.06 55.33,82.41 55.33,82.43 55.33,82.43 55.33,82.95 v2(55.16,83.11)
RGMII1_RXC: length 73.4
  TOP w0.102: v2(55.69,83.64) 55.69,83.64 U7.F15
  TOP w0.137: R282.2 35.02,42.42 35.6,42.99 35.6,43 35.64,43.04 35.64,44.19 39.74,48.3 39.74,54.48 v1(39.33,54.9)
  L6_INT_2 w0.102: 53.2,78.42 53.24,78.45 54.57,78.45 55.13,79.02 55.13,80.69 56.05,81.61 56.05,82.73 55.69,83.09 v2(55.69,83.64)
  L6_INT_2 w0.127: v1(39.33,54.9) 39.83,54.9 40.01,54.71 40.01,54.52 40.2,54.33 40.46,54.33 40.65,54.52 40.65,54.71 40.83,54.9 42.07,54.9 42.26,55.09 42.51,55.09 43.27,54.33 43.61,54.33 43.77,54.49 43.77,54.74 42.97,55.54 42.97,55.8 43.16,55.99 43.42,55.99 44.21,55.2 44.47,55.2 44.66,55.39 44.66,55.65 43.87,56.44 43.87,56.7 44.16,56.99 44.16,57.24 44.34,57.43 46.03,57.43 46.24,57.64 46.24,57.86 46.04,58.06 44.34,58.06 44.16,58.25 44.16,58.62 44.34,58.81 46.09,58.81 46.28,58.99 46.28,59.25 46.09,59.44 44.34,59.44 44.16,59.63 44.16,59.88 44.34,60.07 46.09,60.07 46.28,60.25 46.28,60.52 46.09,60.7 44.34,60.7 44.16,60.89 44.16,61.18 44.68,61.7 44.94,61.7 45.42,61.22 45.68,61.22 45.87,61.4 45.87,61.67 45.39,62.15 45.39,62.41 49.86,66.88 49.86,75.07 53.2,78.42
RGMII1_RXD0: length 73.5
  TOP w0.102: U7.E14 v2(55.69,82.58)
  TOP w0.137: R278.2 33.63,41.37 33.63,42 33.82,42.19 34.2,42.19 34.39,42.37 34.39,42.64 34.2,42.82 33.82,42.82 33.64,43 33.64,43.2 38.98,48.54 38.98,54.21 38.63,54.57 38.27,54.57 37.28,53.57 36.87,53.57 36.44,54 36.44,54.77 37.15,55.48 38.18,55.48 v1(38.52,55.14)
  L6_INT_2 w0.102: 49.4,82.35 49.64,82.58 50.76,82.58 51.19,82.15 51.19,80.96
  L6_INT_2 w0.127: 49.4,82.35 49.4,81.6 50.63,80.37 50.63,78.12 50.51,77.99 50.29,77.99 50.06,78.22 49.8,78.22 49.61,78.03 49.61,77.77 49.84,77.54 49.84,77.28 49.66,77.09 49.4,77.09 49.17,77.32 48.9,77.32 48.72,77.14 48.72,76.87 48.95,76.64 48.95,76.38 48.45,75.89 48.45,67.89 47.89,67.33 47.89,67.07 47.94,67.02 47.94,66.76 47.75,66.57 47.49,66.57 47.44,66.62 47.18,66.62 46.99,66.43 46.99,66.17 47.04,66.12 47.04,65.86 46.85,65.67 46.59,65.67 46.54,65.72 46.28,65.72 46.09,65.53 46.09,65.27 46.14,65.22 46.14,64.96 45.96,64.77 45.69,64.77 45.64,64.82 45.38,64.82 45.2,64.64 45.2,64.37 45.24,64.32 45.24,64.06 45.06,63.87 44.79,63.87 44.67,64 44.47,64 44.23,63.75 44.23,63.55 44.35,63.43 44.35,63.16 44.16,62.98 43.9,62.98 43.85,63.03 43.59,63.03 42.89,62.33 42.89,57.57 40.8,55.49 38.87,55.49 v1(38.52,55.14) ; 51.19,80.96 51.42,80.74 v1(51.42,78.63)
  BOTTOM w0.102: v2(55.69,82.58) 55.17,82.58 53.6,81.01
  BOTTOM w0.137: 53.6,81.01 52.41,79.82 52.41,79.45 51.59,78.63 v1(51.42,78.63)
RGMII1_RXD1: length 73.8
  TOP w0.102: U7.F14 v2(56.22,83.11)
  TOP w0.137: R279.2 32.73,43.13 38.25,48.65 38.25,53.67 v1(38.4,53.82)
  L6_INT_2 w0.102: v2(56.22,83.11) 56.48,82.86 56.48,81.75 55.34,80.61 55.34,80.31 55.93,79.72 55.93,78.7 55.29,78.06 53.67,78.06 53.62,78
  L6_INT_2 w0.127: v1(38.4,53.82) 30.75,53.82 30.62,53.95 30.62,54.55 30.75,54.67 38.16,54.67 38.27,54.57 38.77,54.57 39.59,53.75 43.85,53.75 46.44,56.33 46.44,57 46.86,57.43 46.86,62.72 50.61,66.46 50.61,74.99 53.62,78
RGMII1_RXD2: length 72.6
  TOP w0.102: v2(56.22,80.99) 56.22,80.99 U7.D13
  TOP w0.137: v1(37.79,53.16) 37.3,52.67 37.3,48.58 31.59,42.87 R280.2
  L6_INT_2 w0.102: 55.58,76.48 56.06,76.48 56.58,77 56.58,80.08 56.22,80.43 v2(56.22,80.99)
  L6_INT_2 w0.127: v1(37.79,53.16) 44.09,53.16 47.92,56.99 47.92,57.74 48.1,57.93 49.05,57.93 49.29,58.17 49.29,58.39 49.12,58.57 48.1,58.57 47.92,58.75 47.92,59.01 48.1,59.2 49.26,59.2 49.47,59.41 49.47,59.67 49.3,59.84 47.64,59.84 47.46,60.02 47.46,60.28 47.64,60.47 49.1,60.47 49.22,60.6 49.22,60.98 49.1,61.11 47.64,61.11 47.48,61.27 47.48,61.53 47.68,61.74 49.02,61.74 49.22,61.94 49.22,62.2 49.04,62.38 48.1,62.38 47.92,62.56 47.92,62.95 48.23,63.26 48.67,63.26 49.11,62.82 49.36,62.82 49.53,62.99 49.53,63.63 49.16,64 49.16,64.18 51.63,66.66 51.63,66.96 51.45,67.15 51.38,67.15 51.19,67.33 51.19,67.6 51.38,67.78 51.45,67.78 51.63,67.97 51.63,68.23 51.45,68.42 51.38,68.42 51.19,68.6 51.19,68.87 51.38,69.05 51.45,69.05 51.63,69.24 51.63,69.5 51.45,69.69 51.38,69.69 51.19,69.87 51.19,70.14 51.38,70.32 51.45,70.32 51.63,70.51 51.63,70.77 51.45,70.96 51.38,70.96 51.19,71.14 51.19,71.41 51.38,71.59 51.45,71.59 51.63,71.78 51.63,72.04 51.45,72.23 51.38,72.23 51.19,72.41 51.19,72.68 51.38,72.86 51.45,72.86 51.63,73.05 51.63,75.2 52.92,76.48 54.26,76.48 54.45,76.67 54.45,77.09 54.63,77.28 54.9,77.28 55.08,77.09 55.08,76.67 55.27,76.48 55.58,76.48
RGMII1_RXD3: length 73.3
  TOP w0.102: U7.E13 v2(56.75,81.52)
  TOP w0.137: R281.2 30.45,42.82 36.44,48.81 36.44,52.86 v1(36.47,52.86)
  L6_INT_2 w0.102: v2(56.75,81.52) 57.13,81.15 57.13,80.28 56.93,80.08 56.93,79.78 57.13,79.58 57.13,79.22 56.93,79.02 56.93,76.51 56.33,75.91 55.71,75.91
  L6_INT_2 w0.127: v1(36.47,52.86) 36.75,52.58 44.53,52.58 50.08,58.13 50.08,59.36 50.26,59.54 50.92,59.54 51.11,59.73 51.11,59.99 50.92,60.18 50,60.18 49.83,60.35 49.83,60.61 50.03,60.81 50.92,60.81 51.11,61 51.11,61.26 50.92,61.45 50,61.45 49.83,61.62 49.83,61.88 50.03,62.08 50.92,62.08 51.11,62.27 51.11,62.53 50.92,62.72 50.26,62.72 50.12,62.86 50.12,63.87 50.49,64.25 50.67,64.25 51.26,63.65 51.44,63.65 51.71,63.92 51.71,64.1 51.06,64.76 51.06,65.02 51.24,65.21 51.51,65.21 52.06,64.66 52.37,64.66 52.53,64.82 52.53,65.09 51.95,65.66 51.95,65.92 52.22,66.19 52.22,71.6 52.46,71.84 54.37,71.84 54.62,72.09 54.62,72.42 54.49,72.55 52.47,72.55 52.23,72.79 52.23,74.96 53.16,75.89 55.7,75.89 55.71,75.91
RGMII1_TX_CTL: length 61.2
  TOP w0.137: U13.37 32.1,37.71 v1(32.03,37.78)
  L3_INT_1 w0.127: v1(41.93,55.65) 41.93,54.53 38.12,50.73 38.12,42.6 37.34,41.82 37.34,41.56 37.86,41.04 37.86,40.78 37.67,40.59 37.41,40.59 36.89,41.11 36.63,41.11 36.44,40.92 36.44,40.66 36.96,40.14 36.96,39.88 36.77,39.69 36.51,39.69 35.99,40.21 35.73,40.21 34.44,38.92 34.44,38.14 34.12,37.82 33.54,37.82 33.3,38.07 33.07,38.07 32.7,37.69 32.7,37.43 33.7,36.43 33.7,36.14 33.23,35.67 32.3,35.67 31.32,36.65 31.32,37.07 v1(32.03,37.78)
  L6_INT_2 w0.127: v1(51.38,77.87) 51.34,77.87 49.18,75.72 49.18,67.62 49.22,67.58 49.22,67.21 49.18,67.17 49.18,67.1 43.52,61.44 43.52,57.25 v1(41.93,55.65)
  BOTTOM w0.137: v1(51.38,77.87) 51.35,77.87 51.2,78.02 51.14,78.02 50.61,78.54 50.61,78.86 50.91,79.15 R532.1
RGMII1_TXC: length 60.5
  TOP w0.137: U13.29 36.28,41.38 36.56,41.66 36.56,42.05 36.56,42.05 36.56,44.1 44.27,51.81 44.27,54.28 43.98,54.57 43.07,54.57 42.94,54.44 42.94,53.63 42.75,53.44 42.49,53.44 42.3,53.63 42.3,54.43 42.17,54.57 41.8,54.57 41.67,54.43 41.67,53.63 41.48,53.44 41.22,53.44 41.03,53.63 41.03,54.38 40.86,54.56 40.63,54.56 38.58,56.6 38.58,58.14 38.91,58.47 v1(41.72,58.47)
  L6_INT_2 w0.127: v1(41.72,58.47) 41.67,58.52 41.67,62.95 47.23,68.51 47.23,77.38 48.96,79.11 v1(48.96,79.83)
  BOTTOM w0.137: v1(48.96,79.83) 49.21,79.59 49.57,79.59 R527.1
RGMII1_TXD0: length 57.3
  TOP w0.137: v1(39.29,56.76) 40.87,55.18 44.49,55.18 44.87,54.8 44.87,51.57 37.19,43.89 37.19,41.1 36.78,40.68 U13.28
  L6_INT_2 w0.127: v1(39.29,56.76) 38.15,57.89 38.15,64.95 44.7,71.5 44.7,78.52 46.18,79.99 46.53,79.99 46.58,80.04 v1(46.63,80.04)
  BOTTOM w0.137: 46.85,83.05 46.43,82.63 46.43,80.24 v1(46.63,80.04)
RGMII1_TXD1: length 61.3
  TOP w0.137: U13.27 37.28,39.83 37.97,40.52 37.97,43.82 45.69,51.54 45.69,55.16 44.39,56.45 40.9,56.45 v1(40.03,57.33)
  L6_INT_2 w0.127: v1(47.62,81.43) 48.01,81.04 48.01,79.81 46.07,77.86 46.07,70.69 43.42,68.05 43.42,66.59 41.58,64.76 39.64,64.76 39.32,64.44 39.32,64.11 39.51,63.92 39.99,63.92 40.18,63.73 40.18,63.47 39.99,63.29 39.51,63.29 39.32,63.1 39.32,62.84 39.51,62.65 39.99,62.65 40.18,62.46 40.18,62.2 39.99,62.02 39.51,62.02 39.32,61.83 39.32,61.57 39.51,61.38 39.99,61.38 40.18,61.19 40.18,60.93 39.99,60.75 39.51,60.75 39.32,60.56 39.32,58.48 40.03,57.77 v1(40.03,57.33)
  BOTTOM w0.137: R526.1 47.68,81.5 v1(47.62,81.43)
RGMII1_TXD2: length 58.2
  TOP w0.137: v1(39.12,57.85) 40.51,57.85 41.28,57.08 44.64,57.08 46.3,55.42 46.3,51.12 38.61,43.44 38.61,39.93 37.78,39.1 U13.26
  L6_INT_2 w0.127: v1(39.12,57.85) 38.74,58.23 38.74,64.71 42.8,68.77 43.31,68.77 45.48,70.94 45.48,78.07 45.48,78.1 47.39,80.01 47.39,80.36 v1(46.96,80.78)
  BOTTOM w0.137: v1(46.96,80.78) 47.06,80.88 47.06,81.72 47.56,82.22 R525.1
RGMII1_TXD3: length 62.1
  TOP w0.137: v1(41.47,57.71) 45.22,57.71 47.58,55.36 47.58,51.44 39.2,43.07 39.2,40.97 39.19,40.96 39.19,39.08 38.28,38.16 U13.25
  L6_INT_2 w0.127: v1(48.43,79.4) 46.65,77.62 46.65,70.45 46.39,70.19 46.39,70.18 45.8,69.59 45.8,69.33 46.38,68.75 46.38,68.49 46.2,68.3 45.93,68.3 45.35,68.88 45.09,68.88 44.9,68.7 44.9,68.43 45.48,67.85 45.48,67.59 45.3,67.4 45.03,67.4 44.45,67.98 44.19,67.98 44.01,67.8 44.01,66.12 40.97,63.07 40.97,60.59 40.54,60.16 40.08,60.16 39.9,59.99 39.9,59.76 40.06,59.6 40.82,59.6 40.97,59.46 40.97,59.19 40.84,59.07 40.08,59.07 39.95,58.94 39.95,58.67 40.17,58.45 40.73,58.45 v1(41.47,57.71)
  BOTTOM w0.137: v1(48.43,79.4) 48.43,79.94 48.51,80.02 48.51,80.02 48.78,80.28 48.78,80.28 49.26,80.77
RGMII_TCTRL: length 5.7
  TOP w0.102: U7.E16 55.16,83.64 54.63,83.64 v2(54.63,83.64)
  BOTTOM w0.102: v2(54.63,83.64) 54.63,83.11 53.61,82.09 53.61,81.99
  BOTTOM w0.137: R532.2 51.76,79.83 53.61,81.69 53.61,81.99
RGMII_TD0: length 10.2
  TOP w0.102: U7.F17 v2(54.63,84.71)
  BOTTOM w0.102: 50.74,86.79 50.97,86.79 51.3,86.46 51.63,86.46 51.83,86.66 52.14,86.66 54.1,84.71 v2(54.63,84.71)
  BOTTOM w0.137: R528.2 47.53,84.11 50.21,86.79 50.74,86.79
RGMII_TD1: length 6.6
  TOP w0.102: v2(54.1,84.17) 54.1,84.18 U7.E17
  BOTTOM w0.102: v2(54.1,84.17) 53.95,84.33 53.41,84.33 53.18,84.56 52.9,84.56 52.67,84.33 52.27,84.33 50.74,82.8
  BOTTOM w0.137: R526.2 50.12,82.18 50.74,82.8
RGMII_TD2: length 9
  TOP w0.102: v2(53.57,84.71) 53.57,84.71 U7.E18
  BOTTOM w0.102: 50.51,86.18 50.77,85.93 51.1,85.93 51.35,86.18 51.58,86.18 52.98,84.79 53.49,84.79 v2(53.57,84.71)
  BOTTOM w0.137: 50.51,86.18 50.08,86.18 48.2,84.3 48.2,83.14 R525.2
RGMII_TD3: length 4.9
  TOP w0.102: U7.D18 53.04,84.18 v2(53.04,84.17)
  BOTTOM w0.102: v2(53.04,84.17) 52.92,84.05 52.37,84.05 50.64,82.32
  BOTTOM w0.137: 49.95,81.45 R530.2 49.94,81.63 50.64,82.32
RGMII_TXC: length 7.4
  TOP w0.102: U7.F16 55.16,84.18 v2(55.16,84.17)
  BOTTOM w0.102: v2(55.16,84.17) 54.63,84.17 54.25,83.79 53.97,83.79 53.71,84.05 53.43,84.05 52.67,83.29 51.99,83.29 50.94,82.25
  BOTTOM w0.137: 50.94,82.25 50.69,81.99 R527.2
RTC_XO: length 3.8
  TOP w0.137: X1.2 79.85,85.48 C103.1 78.61,86.72 78.61,87.86 R285.2
RTC_XTALI: length 13.5
  TOP w0.137: U7.AE6 71.73,89.61 74.29,89.61 75.31,90.64 77.19,90.64 R36.1 78.5,89.33 80.63,89.33 C102.1 81.75,88.21 81.75,87.49 X1.1
RTC_XTALO: length 8.2
  TOP w0.137: U7.AD6 71.08,88.42 71.85,89.19 74.55,89.19 75.45,90.09 76.37,90.09 R36.2 R285.1
RX_CLK: length 2.4
  TOP w0.137: R282.1 34.63,39.77 34.63,38.34 34.78,38.2 U13.32
RX_CTRL: length 7
  TOP w0.137: U13.38 31.84,36.79 29.3,39.33 R283.1 R300.2 R306.1
RX_D0: length 2.4
  TOP w0.137: R278.1 34.27,39.77 34.27,38.19 34.28,38.18 U13.33
RX_D1: length 2.6
  TOP w0.137: U13.34 33.78,38.56 32.73,39.6 R279.1
RX_D2: length 3
  TOP w0.137: U13.35 33.28,38.3 32.65,38.92 32.4,38.92 31.59,39.74 R280.1
RX_D3: length 3.4
  TOP w0.137: U13.36 32.78,38.19 32.53,38.44 32.08,38.44 30.45,40.07 R281.1
RX_LED1: length 23.6
  TOP w0.254: D8.1 v1(124.79,121.67)
  L3_INT_1 w0.254: v1(107.76,116.1) 107.79,116.08 122.75,116.08 124.79,118.11 v1(124.79,121.67)
  BOTTOM w0.254: v1(107.76,116.1) 107.76,116.64 107.48,116.92 U18.12
RX_LED2: length 25.7
  TOP w0.254: D10.1 v1(124.72,116.71)
  L3_INT_1 w0.254: v1(117.7,109.09) 124.72,116.12 v1(124.72,116.71)
  BOTTOM w0.254: U18.28 105.98,107.38 107.05,106.3 114.9,106.3 v1(117.7,109.09)
SAI1_MCLK: length 9.9
  TOP w0.102: U7.E10 v2(58.34,79.93)
  BOTTOM w0.137: R110.1 52.19,76.95 55.17,79.93 55.53,79.93 55.9,79.56 57.44,79.56 57.81,79.93 v2(58.34,79.93)
SCHO_MR_B: length 10.4
  TOP w0.254: C382.2 100.35,85.5 R349.1 99.53,86.26 99.53,87.63 99.03,88.13 v1(98.57,88.13) ; D22.1 93.3,88.12 v1(95.03,88.12)
  L3_INT_1 w0.254: v1(95.03,88.12) 98.56,88.12 v1(98.57,88.13)
SCHO_PWR_DISCH: length 13
  BOTTOM w0.254: Q8.3 99.09,50.13 D4.1 98.11,50.81 94.71,50.81 92.42,53.09 R107.2
SD1_CD_B: length 73.6
  TOP w0.102: U7.C6 v2(59.4,76.75)
  L3_INT_1 w0.127: v1(110.2,65.1) 109.27,65.1 98.29,54.12 83.91,54.12 75.76,62.28 73.69,62.28 73.09,62.87 66.69,62.87 61.62,67.94 61.62,69.96 60.87,70.7 60.87,71.5 60.14,72.24 60.14,74.68 59.4,75.41 v2(59.4,76.75)
  BOTTOM w0.137: v1(110.2,65.1) 109.77,65.1 109.13,64.46 R101.2 109.2,64.29 109.59,64.29 109.76,64.45 110.29,64.45 P26.2 110.35,64.39 J28.10
SD1_CLK: length 69.2
  TOP w0.137: v1(60.98,65.51) 59.8,66.69 59.8,70.72 59.21,71.31 59.21,71.31 R49.1
  L3_INT_1 w0.127: v1(109.67,59.19) 109.67,55.68 105.13,51.13 83.89,51.13 75.27,59.75 71.38,59.75 70.92,59.3 68.87,59.3 67.8,60.36 66.66,60.36 62.57,64.45 62.07,64.45 61.01,65.51 v1(60.98,65.51)
  BOTTOM w0.137: v1(109.67,59.19) P24.2 R106.1
SD1_CLK_R: length 3
  BOTTOM w0.137: R106.2 110.21,57.19 C197.1 111.81,56.21 J28.5
SD1_CMD: length 65.4
  TOP w0.137: v1(62.15,63.79) 63.55,65.19 63.55,65.58 R39.1
  L3_INT_1 w0.127: v1(62.15,63.79) 66.16,59.78 66.99,59.78 68.35,58.41 72.51,58.41 73.12,57.8 76.13,57.8 83.3,50.63 105.42,50.63 106.61,51.82 108.73,51.82 110.64,49.91 110.64,48.96 v1(109.54,47.86)
  BOTTOM w0.137: J28.2 110.56,48.96 P25.2 109.98,48.95 R99.2 109.54,48.5 v1(109.54,47.86)
SD1_DATA0: length 66
  TOP w0.137: v1(61.77,65.72) 61.45,66.04 R41.1
  L3_INT_1 w0.127: v1(109.69,61.4) 109.69,60.49 107.39,58.19 107.13,58.19 106.75,58.57 106.49,58.57 106.31,58.38 106.31,58.12 106.68,57.74 106.68,57.48 106.49,57.29 106.23,57.29 105.86,57.67 105.59,57.67 105.41,57.48 105.41,57.22 105.78,56.84 105.78,56.58 105.6,56.39 105.33,56.39 104.96,56.77 104.7,56.77 104.51,56.58 104.51,56.32 104.88,55.95 104.88,55.68 104.7,55.5 104.44,55.5 104.06,55.87 103.8,55.87 103.61,55.69 103.61,55.42 103.99,55.05 103.99,54.78 101.91,52.7 83.36,52.7 75.73,60.34 69.1,60.34 68.18,61.26 66.58,61.26 62.81,65.04 62.31,65.04 61.89,65.46 61.89,65.6 v1(61.77,65.72)
  BOTTOM w0.137: v1(109.69,61.4) P20.2 110.3,61.39 J28.7
SD1_DATA1: length 72.2
  L3_INT_1 w0.127: v1(109.74,63) 100.46,53.72 83.29,53.72 75,62 73.57,62 73.06,62.51 66.26,62.51 63.15,65.62 v1(62.55,65.62)
  BOTTOM w0.137: v1(62.55,65.62) 61.7,64.77 61.7,63.54 61.29,63.12 60.46,63.12 56.1,67.49 56.1,68.95 55.21,69.83 R42.1 ; v1(109.74,63) 109.79,63.05 P21.2 112.02,63.05 J28.8
SD1_DATA2: length 70.8
  TOP w0.137: v1(62.95,62.32) 64.1,63.46 64.1,66.3 R43.1
  L3_INT_1 w0.127: v1(109.44,45.21) 109.64,45.01 112.77,45.01 112.89,45.14 112.89,46.23 112.13,46.99 108.42,46.99 105.25,50.17 104.3,50.17 104.27,50.2 82.82,50.2 76.13,56.9 68.35,56.9 62.95,62.3 v1(62.95,62.32)
  BOTTOM w0.137: J28.9 112.03,44 P22.2 109.44,45.11 v1(109.44,45.21)
SD1_DATA3: length 72.2
  L3_INT_1 w0.127: v1(107.41,46.45) 107.43,46.46 108.29,46.46 108.54,46.21 108.54,45.63 108.27,45.36 105.74,45.36 105.18,45.92 105.18,48.68 104.09,49.77 82.38,49.77 75.84,56.31 68.14,56.31 v1(60.88,63.57)
  BOTTOM w0.137: v1(60.88,63.57) 56.69,67.76 56.69,68.81 55.95,69.55 R44.1 ; J28.1 112.01,46.41 P23.2 110.08,46.41 110.04,46.45 v1(107.41,46.45)
SD1_RESET_B: length 68.8
  TOP w0.127: v1(59.21,73.69) 59.15,73.76 59.15,74.37 59.93,75.16 U7.B4
  L3_INT_1 w0.127: v1(59.21,73.69) 59.21,71.97 60.44,70.74 60.44,63.23 70.2,53.47 77.5,53.47 81.51,49.47 103.89,49.47 104.68,48.68 v1(104.68,47.56)
  BOTTOM w0.137: R491.1 R108.1 106.31,47.56 v1(104.68,47.56)
SD1_WP: length 70
  TOP w0.102: U7.C4 60.46,75.69 v2(60.47,75.69)
  L3_INT_1 w0.127: v1(109.17,66.31) 97.66,54.8 84.46,54.8 76.7,62.56 73.8,62.56 73.18,63.18 66.78,63.18 62.26,67.7 62.26,69.72 61.15,70.82 61.15,71.93 60.47,72.62 v2(60.47,75.69)
  BOTTOM w0.137: v1(109.17,66.31) 109.13,66.27 R100.2 110.26,65.63 P27.2 110.37,65.59 J28.11
SD2_CLK: length 90.9
  TOP w0.137: R176.1 v1(101.24,18.16)
  L3_INT_1 w0.127: v1(58.94,70.13) 59.67,69.4 59.67,62.34 83.34,38.66 83.34,25.56 83.67,25.24 83.93,25.24 84.78,26.08 85.04,26.08 85.22,25.9 85.22,25.63 84.38,24.79 84.38,24.52 84.56,24.34 84.83,24.34 85.67,25.18 85.94,25.18 86.12,25 86.12,24.74 85.28,23.89 85.28,23.63 85.46,23.44 85.72,23.44 86.57,24.29 86.83,24.29 87.02,24.1 87.02,23.84 86.17,22.99 86.17,22.73 86.36,22.54 86.62,22.54 87.47,23.39 87.73,23.39 87.92,23.2 87.92,22.94 87.07,22.09 87.07,21.83 87.26,21.64 87.52,21.64 88.37,22.49 88.63,22.49 88.82,22.3 88.82,22.04 87.97,21.19 87.97,20.93 88.82,20.08 98.53,20.08 98.54,20.07 99.32,20.07 v1(101.24,18.16)
  BOTTOM w0.137: 59.29,70.47 59.51,70.7 R286.1 59.3,70.47 59.29,70.47 ; 59.29,70.47 v1(58.94,70.13)
SD2_CMD: length 92.6
  TOP w0.137: v1(99.15,19.43) R177.1
  L3_INT_1 w0.127: v1(99.15,19.43) 98.9,19.18 98.17,19.18 98.16,19.17 97.91,19.17 97.78,19.04 97.78,18.79 97.6,18.61 97.33,18.61 97.15,18.79 97.15,19.25 96.96,19.43 96.7,19.43 96.51,19.25 96.51,18.79 96.33,18.61 96.06,18.61 95.88,18.79 95.88,19.25 95.69,19.43 95.43,19.43 95.24,19.25 95.24,18.79 95.06,18.61 94.79,18.61 94.61,18.79 94.61,19.25 94.42,19.43 94.16,19.43 93.97,19.25 93.97,18.79 93.79,18.61 93.52,18.61 93.34,18.79 93.34,19.25 93.15,19.43 92.89,19.43 92.7,19.25 92.7,18.79 92.52,18.61 92.25,18.61 92.07,18.79 92.07,19.25 91.88,19.43 91.62,19.43 91.43,19.25 91.43,18.79 91.25,18.61 90.98,18.61 90.8,18.79 90.8,19.25 90.61,19.43 90.35,19.43 90.16,19.25 90.16,18.79 89.98,18.61 89.71,18.61 89.53,18.79 89.53,19.25 89.34,19.43 89.08,19.43 88.89,19.25 88.89,18.79 88.71,18.61 88.44,18.61 88.26,18.79 88.26,19.25 88.07,19.43 87.74,19.43 82.16,25.01 82.16,37.73 64.53,55.36 64.53,56.59 59.08,62.04 59.08,69.02 58.35,69.74 58.35,70.47 58.61,70.73 58.61,71.26 58.27,71.6 57.78,71.6 57.76,71.57 v1(57.55,71.57)
  BOTTOM w0.137: R287.1 57.55,71.94 v1(57.55,71.57) ; R177.1 v1(99.15,19.43)
SD2_DATA0: length 88.3
  TOP w0.137: v1(101.19,17.02) R178.1
  L3_INT_1 w0.127: v1(101.19,17.02) 100.12,17.02 99.94,17.2 99.94,17.53 99.75,17.72 99.49,17.72 99.3,17.53 99.3,17.2 99.12,17.02 98.9,17.02 98.53,17.38 98.17,17.38 97.8,17.02 97.58,17.02 97.4,17.2 97.4,17.53 97.21,17.72 96.95,17.72 96.76,17.53 96.76,17.2 96.58,17.02 96.31,17.02 96.13,17.2 96.13,17.53 95.94,17.72 95.68,17.72 95.49,17.53 95.49,17.2 95.31,17.02 95.04,17.02 94.86,17.2 94.86,17.53 94.67,17.72 94.41,17.72 94.22,17.53 94.22,17.2 94.04,17.02 93.77,17.02 93.59,17.2 93.59,17.53 93.4,17.72 93.14,17.72 92.95,17.53 92.95,17.2 92.77,17.02 92.5,17.02 92.32,17.2 92.32,17.53 92.13,17.72 91.87,17.72 91.68,17.53 91.68,17.2 91.5,17.02 91.23,17.02 91.05,17.2 91.05,17.53 90.86,17.72 90.6,17.72 90.41,17.53 90.41,17.2 90.23,17.02 89.96,17.02 89.78,17.2 89.78,17.53 89.59,17.72 89.33,17.72 89.14,17.53 89.14,17.2 88.96,17.02 88.52,17.02 81.05,24.49 81.05,38.01 63.95,55.11 63.95,56.35 58.49,61.8 v1(58.49,68.78)
  BOTTOM w0.137: R288.1 57.74,69.53 v1(58.49,68.78) ; R178.1 v1(101.19,17.02)
